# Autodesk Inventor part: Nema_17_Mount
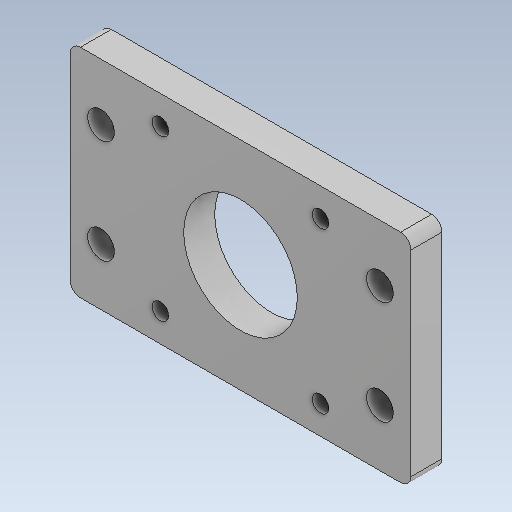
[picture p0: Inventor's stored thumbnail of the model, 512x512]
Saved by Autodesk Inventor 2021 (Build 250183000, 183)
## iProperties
Created: 2026-10
Part Number: Nema_17_Mount
Material: Steel
Document SubType Name: Modeling
Designer: hp
Density: 7.85 g/cm^3
Appearance: Default
Author: hp
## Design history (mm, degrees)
feature "Body1"
body "Solid1"
